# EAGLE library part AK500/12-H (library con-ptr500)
CONNECTOR Aug. 2004 / PTR Meßtechnik: Die Bezeichnung der Serie AK505 wurde geändert. Es handelt sich hierbei um AK500 in horizontaler Ausführung.
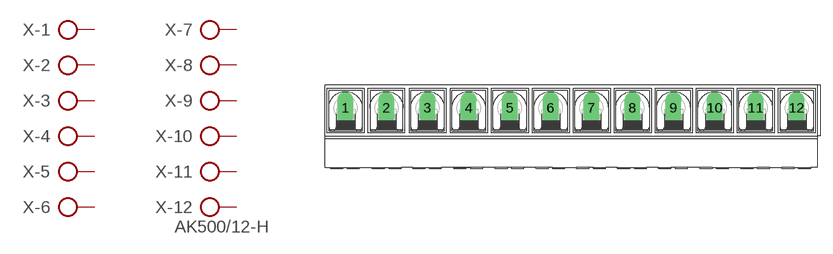
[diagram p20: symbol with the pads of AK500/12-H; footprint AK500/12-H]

Designator prefix X; gates -1=KL -2=KL -3=KL -4=KL -5=KL -6=KL -7=KL -8=KL -9=KL -10=KL -11=KL -12=KLV

## AK500/12-H (OC_FARNELL: unknown; OC_NEWARK: unknown)  [AK500/12-H]
1  -1:KL  pas
2  -2:KL  pas
3  -3:KL  pas
4  -4:KL  pas
5  -5:KL  pas
6  -6:KL  pas
7  -7:KL  pas
8  -8:KL  pas
9  -9:KL  pas
10  -10:KL  pas
11  -11:KL  pas
12  -12:KL  pas

## Footprint AK500/12-H (pad centres in mm)
CONNECTOR Aug. 2004 / PTR Meßtechnik: Die Bezeichnung der Serie AK505 wurde geändert. Es handelt sich hierbei um AK500 in horizontaler Ausführung.
drill 1.321 long: 1 -27.534,0; 2 -22.53,0; 3 -17.526,0; 4 -12.497,0; 5 -7.493,0; 6 -2.489,0; 7 2.489,0; 8 7.493,0; 9 12.497,0; 10 17.526,0; 11 22.53,0; 12 27.534,0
